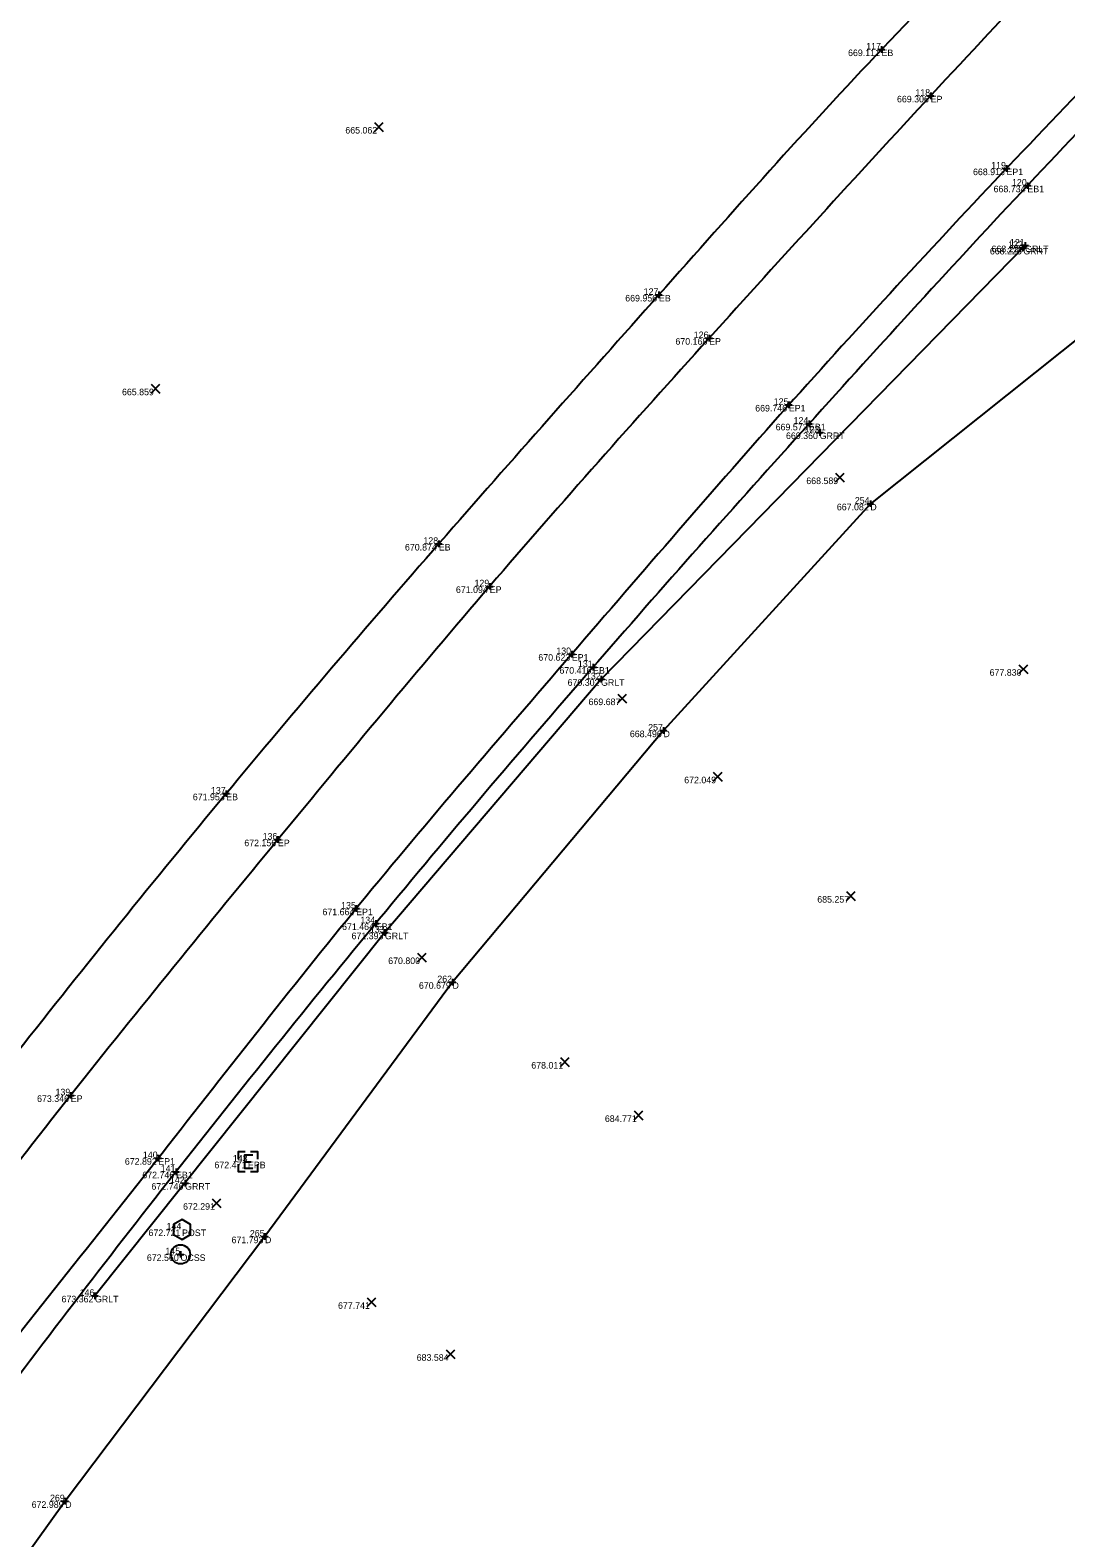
# Model space of a CAD drawing. Extents: x 2197382 to 2204062, y 634117 to 636522.
# Drawn here: x 2202306.8 to 2202463.8, y 634830.5 to 635059.1 of the extents above; entities that cross this region are included whole.
import ezdxf

# ---------------------------------------------------------------- set-up
doc = ezdxf.new("R2010")
doc.units = 0
for name, color, linetype in [('_CIVIL_CONSTRUCTION', 7, 'Continuous'), ('DR_X_Ditch', 7, 'Continuous'), ('GE_P_Alignment_100_Bearings', 7, 'Continuous'), ('GE_P_Alignment_100_Distances', 7, 'Continuous'), ('GE_X_Alignment', 7, 'Continuous'), ('PF_X_Ground_Line', 7, 'Continuous'), ('RW_X_CL_100_Bearings', 7, 'Continuous'), ('RW_X_CL_100_Cardinal_Points', 7, 'Continuous'), ('RW_X_CL_100_Curve_Data', 7, 'Continuous'), ('SH_Border', 7, 'Continuous'), ('SH_Cut_Line', 7, 'Continuous'), ('SH_Data', 7, 'Continuous')]:
    doc.layers.add(name, color=color, linetype=linetype)

msp = doc.modelspace()

# ---------------------------------------------------------------- linework, layer by layer
at = {"layer": '_CIVIL_CONSTRUCTION'}
for p, q in [((2202435.38, 635056.14), (2202436.38, 635056.14)), ((2202435.88, 635056.64), (2202435.88, 635055.64)), ((2202435.88, 635056.14), (2202435.88, 635056.14)), ((2202442.83, 635049.12), (2202443.83, 635049.12)), ((2202443.33, 635049.62), (2202443.33, 635048.62)), ((2202443.33, 635049.12), (2202443.33, 635049.12)), ((2202454.32, 635038.09), (2202455.32, 635038.09)), ((2202454.82, 635038.59), (2202454.82, 635037.59)), ((2202454.82, 635038.09), (2202454.82, 635038.09)), ((2202457.5, 635035.5), (2202458.5, 635035.5)), ((2202458, 635036), (2202458, 635035)), ((2202458, 635035.5), (2202458, 635035.5)), ((2202456.88, 635026.07), (2202457.88, 635026.07)), ((2202457.15, 635026.41), (2202458.15, 635026.41)), ((2202457.38, 635026.57), (2202457.38, 635025.57)), ((2202457.38, 635026.07), (2202457.38, 635026.07)), ((2202457.65, 635026.91), (2202457.65, 635025.91)), ((2202457.65, 635026.41), (2202457.65, 635026.41)), ((2202402.12, 635019.44), (2202402.12, 635018.44)), ((2202401.62, 635018.94), (2202402.62, 635018.94)), ((2202402.12, 635018.94), (2202402.12, 635018.94)), ((2202409.23, 635012.38), (2202410.23, 635012.38)), ((2202409.73, 635012.88), (2202409.73, 635011.88)), ((2202409.73, 635012.38), (2202409.73, 635012.38)), ((2202421.32, 635002.26), (2202422.32, 635002.26)), ((2202421.82, 635002.76), (2202421.82, 635001.76)), ((2202421.82, 635002.26), (2202421.82, 635002.26)), ((2202424.38, 634999.4), (2202425.38, 634999.4)), ((2202424.88, 634999.9), (2202424.88, 634998.9)), ((2202424.88, 634999.4), (2202424.88, 634999.4)), ((2202426, 634998.08), (2202427, 634998.08)), ((2202426.5, 634998.58), (2202426.5, 634997.58)), ((2202426.5, 634998.08), (2202426.5, 634998.08)), ((2202433.68, 634987.28), (2202434.68, 634987.28)), ((2202434.18, 634987.78), (2202434.18, 634986.78)), ((2202434.18, 634987.28), (2202434.18, 634987.28)), ((2202368.23, 634981.18), (2202369.23, 634981.18)), ((2202368.73, 634981.68), (2202368.73, 634980.68)), ((2202368.73, 634981.18), (2202368.73, 634981.18)), ((2202375.96, 634974.75), (2202376.96, 634974.75)), ((2202376.46, 634975.25), (2202376.46, 634974.25)), ((2202376.46, 634974.75), (2202376.46, 634974.75)), ((2202388.4, 634964.47), (2202389.4, 634964.47)), ((2202388.9, 634964.97), (2202388.9, 634963.97)), ((2202388.9, 634964.47), (2202388.9, 634964.47)), ((2202391.63, 634962.5), (2202392.63, 634962.5)), ((2202392.13, 634963), (2202392.13, 634962)), ((2202392.13, 634962.5), (2202392.13, 634962.5)), ((2202392.84, 634960.67), (2202393.84, 634960.67)), ((2202393.34, 634961.17), (2202393.34, 634960.17)), ((2202393.34, 634960.67), (2202393.34, 634960.67)), ((2202402.81, 634953.38), (2202402.81, 634952.38)), ((2202402.31, 634952.88), (2202403.31, 634952.88)), ((2202402.81, 634952.88), (2202402.81, 634952.88)), ((2202336.5, 634943.82), (2202336.5, 634942.82)), ((2202336, 634943.32), (2202337, 634943.32)), ((2202336.5, 634943.32), (2202336.5, 634943.32)), ((2202343.84, 634936.35), (2202344.84, 634936.35)), ((2202344.34, 634936.85), (2202344.34, 634935.85)), ((2202344.34, 634936.35), (2202344.34, 634936.35)), ((2202355.71, 634925.89), (2202356.71, 634925.89)), ((2202356.21, 634926.39), (2202356.21, 634925.39)), ((2202356.21, 634925.89), (2202356.21, 634925.89)), ((2202358.68, 634923.65), (2202359.68, 634923.65)), ((2202359.18, 634924.15), (2202359.18, 634923.15)), ((2202359.18, 634923.65), (2202359.18, 634923.65)), ((2202360.06, 634922.25), (2202361.06, 634922.25)), ((2202360.56, 634922.75), (2202360.56, 634921.75)), ((2202360.56, 634922.25), (2202360.56, 634922.25)), ((2202370.31, 634914.73), (2202371.31, 634914.73)), ((2202370.81, 634915.23), (2202370.81, 634914.23)), ((2202370.81, 634914.73), (2202370.81, 634914.73)), ((2202312.92, 634898.08), (2202312.92, 634897.08)), ((2202312.42, 634897.58), (2202313.42, 634897.58)), ((2202312.92, 634897.58), (2202312.92, 634897.58)), ((2202325.69, 634888.06), (2202326.69, 634888.06)), ((2202326.19, 634888.56), (2202326.19, 634887.56)), ((2202326.19, 634888.06), (2202326.19, 634888.06)), ((2202328.38, 634886), (2202329.38, 634886)), ((2202328.88, 634886.5), (2202328.88, 634885.5)), ((2202328.88, 634886), (2202328.88, 634886)), ((2202330.26, 634884.77), (2202330.26, 634883.77)), ((2202329.76, 634884.27), (2202330.76, 634884.27)), ((2202330.26, 634884.27), (2202330.26, 634884.27)), ((2202341.87, 634876.16), (2202342.87, 634876.16)), ((2202342.37, 634876.66), (2202342.37, 634875.66)), ((2202342.37, 634876.16), (2202342.37, 634876.16)), ((2202329.07, 634873.47), (2202330.07, 634873.47)), ((2202329.57, 634873.97), (2202329.57, 634872.97)), ((2202329.57, 634873.47), (2202329.57, 634873.47)), ((2202316.09, 634867.18), (2202317.09, 634867.18)), ((2202316.59, 634867.68), (2202316.59, 634866.68)), ((2202316.59, 634867.18), (2202316.59, 634867.18)), ((2202312.08, 634836.54), (2202312.08, 634835.54)), ((2202311.58, 634836.04), (2202312.58, 634836.04)), ((2202312.08, 634836.04), (2202312.08, 634836.04))]:
    msp.add_line(p, q, dxfattribs=at)
at = {"layer": 'DR_X_Ditch'}
msp.add_lwpolyline([(2202500.41, 635039.09), (2202475.63, 635020.32), (2202434.18, 634987.28), (2202402.81, 634952.88), (2202370.81, 634914.73), (2202342.37, 634876.16), (2202312.08, 634836.04), (2202284.91, 634798.23), (2202254.23, 634756.84), (2202226.56, 634714.46), (2202198.47, 634675.43), (2202174.83, 634632.13), (2202164.13, 634613.64)], dxfattribs=at)
at = {"layer": 'GE_P_Alignment_100_Bearings'}
msp.add_circle((2202329.57, 634873.47), 1.46, dxfattribs=at)
at = {"layer": 'GE_P_Alignment_100_Distances'}
for points in [[(2202514.19, 635120), (2202501.95, 635108.79), (2202477.63, 635085.87), (2202443.41, 635049.36), (2202409.55, 635012.34), (2202376.26, 634974.99), (2202344.34, 634936.42), (2202312.72, 634897.79), (2202282.43, 634858.12), (2202252.58, 634818.18), (2202223.74, 634777.45), (2202196.69, 634735.5), (2202169.8, 634693.41), (2202144.64, 634650.36), (2202119.18, 634607.44), (2202097.03, 634562.79), (2202074.71, 634518.18), (2202053.15, 634473.28), (2202032.85, 634427.72), (2202013.67, 634381.72), (2201995.41, 634335.21), (2201979.19, 634288.02), (2201963.55, 634240.68), (2201953.92, 634208.98), (2201949.13, 634193.1)], [(2202525.02, 635108.11), (2202513.04, 635097.11), (2202489.33, 635074.07), (2202455.07, 635038.62), (2202421.29, 635002.1), (2202388.81, 634964.35), (2202356.35, 634926.75), (2202325.87, 634887.43), (2202295, 634848.95), (2202265.53, 634808.92), (2202237.35, 634768.89), (2202211.52, 634726.54), (2202183.6, 634685.47), (2202158.14, 634642.34), (2202133.69, 634599.43), (2202111.05, 634555.42), (2202088.76, 634511.33), (2202068.04, 634466.33), (2202047.21, 634421.56), (2202027.88, 634376.06), (2202010.16, 634329.7), (2201994.09, 634282.81), (2201978.74, 634235.43), (2201968.75, 634203.87), (2201963.85, 634187.95)]]:
    msp.add_open_spline(points, degree=3, dxfattribs=at)
at = {"layer": 'GE_X_Alignment'}
for points in [[(2202540.06, 635152.93), (2202529.43, 635144.25), (2202507.23, 635123.46), (2202471.72, 635092.05), (2202435.62, 635056.76), (2202402.1, 635018.87), (2202368.73, 634981.48), (2202336.15, 634943.25), (2202304.62, 634904.21), (2202274.11, 634864.33), (2202244.37, 634823.83), (2202215.65, 634782.83), (2202187.65, 634741.05), (2202161.54, 634698.56), (2202134.84, 634656), (2202111.41, 634611.66), (2202087.71, 634567.52), (2202064.97, 634523.35), (2202044.2, 634477.97), (2202023.42, 634432.25), (2202003.66, 634386.18), (2201990.91, 634355.55), (2201984.79, 634340.33)], [(2202570.92, 635145.14), (2202556.1, 635132.41), (2202530.6, 635107.02), (2202492.19, 635071.28), (2202457.98, 635035.82), (2202424.73, 634999.38), (2202391.64, 634962.22), (2202359.56, 634924.46), (2202328.32, 634885.6), (2202298.37, 634846.53), (2202268.85, 634806.21), (2202240.94, 634765.59), (2202212.91, 634724.71), (2202187.2, 634682.69), (2202161.14, 634640.35), (2202137.99, 634596.95), (2202114.64, 634553.56), (2202092.28, 634509.95), (2202071.73, 634464.7), (2202050.81, 634420.11), (2202031.84, 634374.34), (2202014.23, 634328.21), (2201997.98, 634281.03), (2201983.22, 634233.69), (2201972.74, 634202.38), (2201968.03, 634186.79)]]:
    msp.add_open_spline(points, degree=3, dxfattribs=at)
at = {"layer": 'PF_X_Ground_Line'}
msp.add_lwpolyline([(2202457.65, 635026.41), (2202393.34, 634960.67), (2202360.56, 634922.25), (2202316.59, 634867.18)], dxfattribs=at)
at = {"layer": 'RW_X_CL_100_Bearings'}
for p, q in [((2202339.29, 634887.52), (2202340.29, 634887.52)), ((2202339.79, 634887.52), (2202339.79, 634887.52))]:
    msp.add_line(p, q, dxfattribs=at)
for points in [[(2202339.39, 634889.02), (2202338.29, 634889.02), (2202338.29, 634887.92)], [(2202341.29, 634887.92), (2202341.29, 634889.02), (2202340.19, 634889.02)], [(2202338.29, 634887.12), (2202338.29, 634886.02), (2202339.39, 634886.02)], [(2202340.54, 634888.52), (2202339.29, 634888.52), (2202339.29, 634886.52), (2202340.54, 634886.52)], [(2202340.19, 634886.02), (2202341.29, 634886.02), (2202341.29, 634887.12)]]:
    msp.add_lwpolyline(points, dxfattribs=at)
at = {"layer": 'RW_X_CL_100_Cardinal_Points'}
msp.add_lwpolyline([(2202328.5, 634876.49), (2202329.8, 634875.74), (2202331.09, 634876.49), (2202331.09, 634877.99), (2202329.8, 634878.74), (2202328.5, 634877.99), (2202328.5, 634876.49)], dxfattribs=at)
at = {"layer": 'RW_X_CL_100_Curve_Data'}
for p, q in [((2202358.97, 635043.73), (2202360.3, 635045.07)), ((2202358.97, 635045.07), (2202360.3, 635043.73)), ((2202325.1, 635004.06), (2202326.44, 635005.39)), ((2202325.1, 635005.39), (2202326.44, 635004.06)), ((2202428.89, 634990.58), (2202430.22, 634991.91)), ((2202428.89, 634991.91), (2202430.22, 634990.58)), ((2202456.72, 634961.52), (2202458.05, 634962.86)), ((2202456.72, 634962.86), (2202458.05, 634961.52)), ((2202395.87, 634957.07), (2202397.2, 634958.4)), ((2202395.87, 634958.4), (2202397.2, 634957.07)), ((2202410.36, 634945.22), (2202411.7, 634946.56)), ((2202410.36, 634946.56), (2202411.7, 634945.22)), ((2202430.56, 634927.12), (2202431.89, 634928.46)), ((2202430.56, 634928.46), (2202431.89, 634927.12)), ((2202365.51, 634917.81), (2202366.84, 634919.15)), ((2202365.51, 634919.15), (2202366.84, 634917.81)), ((2202387.17, 634901.97), (2202388.51, 634903.3)), ((2202387.17, 634903.3), (2202388.51, 634901.97)), ((2202398.34, 634893.88), (2202399.67, 634895.21)), ((2202398.34, 634895.21), (2202399.67, 634893.88)), ((2202334.36, 634880.57), (2202335.69, 634881.9)), ((2202334.36, 634881.9), (2202335.69, 634880.57)), ((2202357.87, 634865.54), (2202359.2, 634866.88)), ((2202357.87, 634866.88), (2202359.2, 634865.54)), ((2202369.83, 634857.66), (2202371.17, 634858.99)), ((2202369.83, 634858.99), (2202371.17, 634857.66))]:
    msp.add_line(p, q, dxfattribs=at)

# ---------------------------------------------------------------- texts
at = {"layer": 'SH_Border'}
for s, p in [('EB', (2202435.88, 635055.14)), ('EP', (2202443.33, 635048.12)), ('EP1', (2202454.82, 635037.09)), ('EB1', (2202458, 635034.5)), ('GRRT', (2202457.38, 635025.07)), ('GRLT', (2202457.65, 635025.41)), ('EB', (2202402.12, 635017.94)), ('EP', (2202409.73, 635011.38)), ('EP1', (2202421.82, 635001.26)), ('EB1', (2202424.88, 634998.4)), ('GRRT', (2202426.5, 634997.08)), ('D', (2202434.18, 634986.28)), ('EB', (2202368.73, 634980.18)), ('EP', (2202376.46, 634973.75)), ('EP1', (2202388.9, 634963.47)), ('EB1', (2202392.13, 634961.5)), ('GRLT', (2202393.34, 634959.67)), ('D', (2202402.81, 634951.88)), ('EB', (2202336.5, 634942.32)), ('EP', (2202344.34, 634935.35)), ('EP1', (2202356.21, 634924.89)), ('EB1', (2202359.18, 634922.65)), ('GRLT', (2202360.56, 634921.25)), ('D', (2202370.81, 634913.73)), ('EP', (2202312.92, 634896.58)), ('EP1', (2202326.19, 634887.06)), ('EPB', (2202339.79, 634886.52)), ('EB1', (2202328.88, 634885)), ('GRRT', (2202330.26, 634883.27)), ('POST', (2202329.8, 634876.24)), ('D', (2202342.37, 634875.16)), ('OCSS', (2202329.57, 634872.47)), ('GRLT', (2202316.59, 634866.19)), ('D', (2202312.08, 634835.04))]:
    msp.add_text(s, height=1, dxfattribs=at).set_placement(p)
at = {"layer": 'SH_Cut_Line'}
for s, p in [('117', (2202433.56, 635056.14)), ('118', (2202441.01, 635049.12)), ('119', (2202452.51, 635038.09)), ('120', (2202455.66, 635035.5)), ('122', (2202455.08, 635026.07)), ('121', (2202455.35, 635026.41)), ('127', (2202399.8, 635018.94)), ('126', (2202407.4, 635012.38)), ('125', (2202419.53, 635002.26)), ('124', (2202422.54, 634999.4)), ('123', (2202424.22, 634998.08)), ('254', (2202431.83, 634987.28)), ('128', (2202366.4, 634981.18)), ('129', (2202374.15, 634974.75)), ('130', (2202386.56, 634964.47)), ('131', (2202389.83, 634962.5)), ('132', (2202391.05, 634960.67)), ('257', (2202400.49, 634952.88)), ('137', (2202334.18, 634943.32)), ('136', (2202342.02, 634936.35)), ('135', (2202353.92, 634925.89)), ('134', (2202356.84, 634923.65)), ('133', (2202358.28, 634922.25)), ('262', (2202368.51, 634914.73)), ('139', (2202310.61, 634897.58)), ('140', (2202323.86, 634888.06)), ('141', (2202326.57, 634886)), ('143', (2202337.5, 634887.52)), ('142', (2202327.96, 634884.27)), ('144', (2202327.45, 634877.24)), ('265', (2202340.08, 634876.16)), ('145', (2202327.28, 634873.47)), ('146', (2202314.27, 634867.18)), ('269', (2202309.77, 634836.04))]:
    msp.add_text(s, height=1, dxfattribs=at).set_placement(p)
at = {"layer": 'SH_Data'}
for s, p in [('669.111', (2202430.8, 635055.14)), ('669.306', (2202438.22, 635048.12)), ('665.062', (2202354.56, 635043.4)), ('668.913', (2202449.75, 635037.09)), ('668.734', (2202452.87, 635034.5)), ('668.225', (2202452.31, 635025.07)), ('668.228', (2202452.55, 635025.41)), ('669.956', (2202397.01, 635017.94)), ('670.168', (2202404.62, 635011.38)), ('665.859', (2202320.69, 635003.72)), ('669.746', (2202416.72, 635001.26)), ('669.573', (2202419.82, 634998.4)), ('669.360', (2202421.39, 634997.08)), ('668.589', (2202424.47, 634990.25)), ('667.082', (2202429.1, 634986.28)), ('670.874', (2202363.6, 634980.18)), ('671.094', (2202371.33, 634973.75)), ('670.623', (2202383.83, 634963.47)), ('670.416', (2202387.03, 634961.5)), ('677.830', (2202452.27, 634961.19)), ('670.302', (2202388.27, 634959.67)), ('669.687', (2202391.44, 634956.74)), ('668.496', (2202397.71, 634951.88)), ('672.049', (2202405.95, 634944.89)), ('671.953', (2202331.43, 634942.32)), ('672.156', (2202339.24, 634935.35)), ('685.257', (2202426.13, 634926.79)), ('671.664', (2202351.09, 634924.89)), ('671.464', (2202354.06, 634922.65)), ('671.393', (2202355.5, 634921.25)), ('670.800', (2202361.06, 634917.48)), ('670.679', (2202365.72, 634913.73)), ('678.011', (2202382.76, 634901.63)), ('673.346', (2202307.81, 634896.58)), ('684.771', (2202393.92, 634893.55)), ('672.892', (2202321.12, 634887.06)), ('672.471', (2202334.71, 634886.52)), ('672.746', (2202323.77, 634885)), ('672.746', (2202325.15, 634883.27)), ('672.291', (2202329.95, 634880.23)), ('672.721', (2202324.71, 634876.24)), ('671.793', (2202337.3, 634875.16)), ('672.560', (2202324.46, 634872.47)), ('673.362', (2202311.52, 634866.19)), ('677.741', (2202353.45, 634865.21)), ('683.584', (2202365.38, 634857.33)), ('672.989', (2202306.99, 634835.04))]:
    msp.add_text(s, height=1, dxfattribs=at).set_placement(p)

doc.saveas('drawing.dxf')
